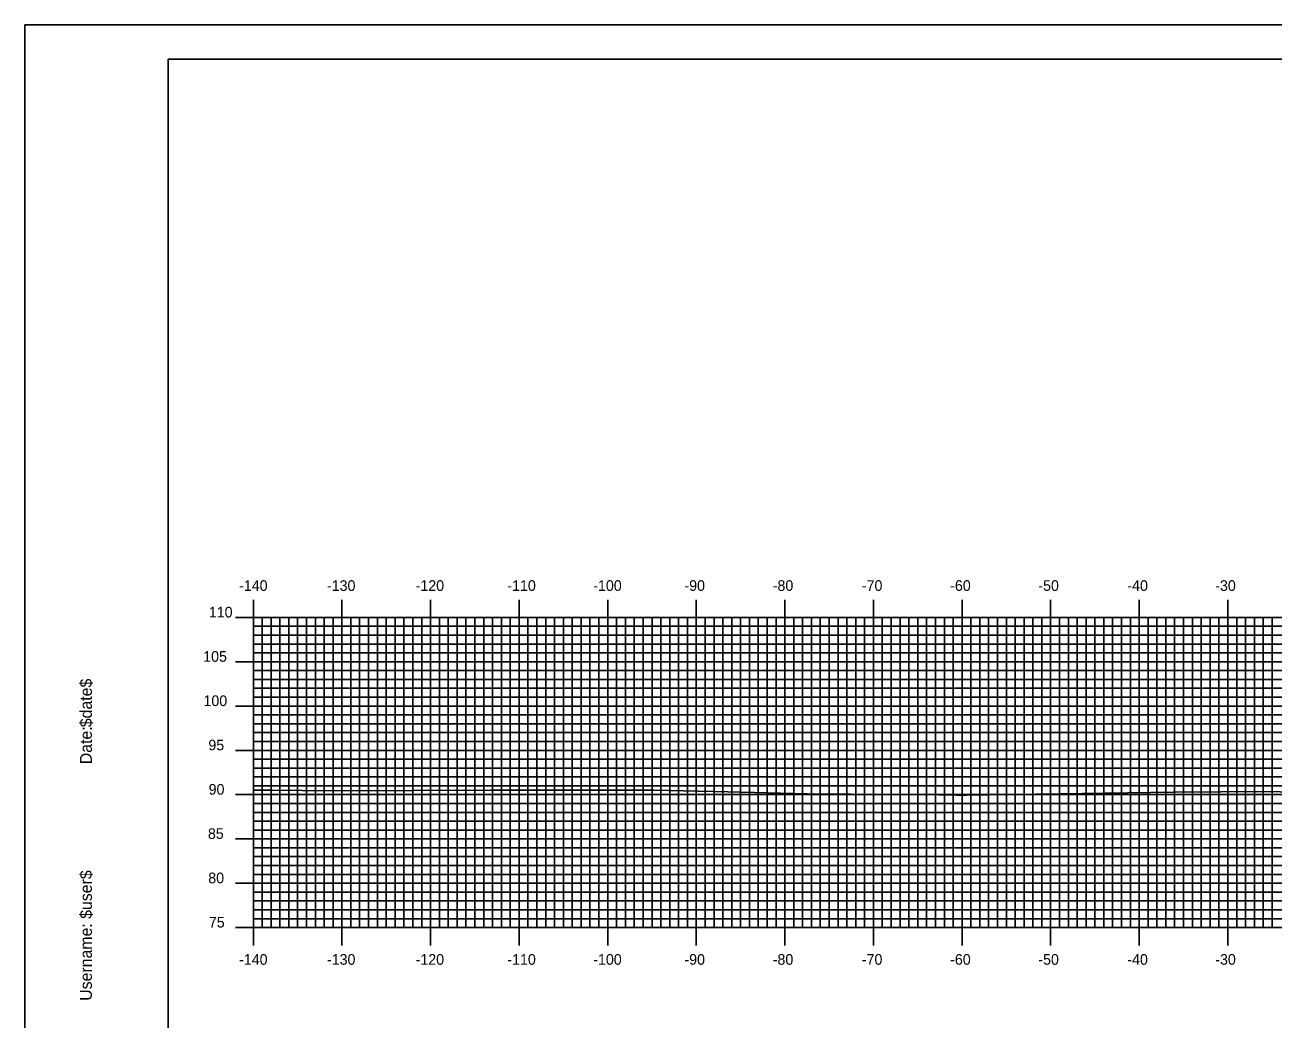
# Model space of a CAD drawing. Extents: x 854510 to 854853, y 364366 to 364586.
# Drawn here: x 854510 to 854650.8, y 364473.5 to 364585.7 of the extents above; entities that cross this region are included whole.
import ezdxf

# ---------------------------------------------------------------- set-up
doc = ezdxf.new("R2010")
doc.units = 0
for name, color, linetype in [('BORDER', 7, 'Continuous'), ('H_V ANNOTATION', 7, 'Continuous'), ('MAJOR', 7, 'Continuous'), ('MINOR', 7, 'Continuous'), ('PLOT BOUNDARY', 7, 'Continuous'), ('S_Roadway_Centerline', 7, 'Continuous')]:
    doc.layers.add(name, color=color, linetype=linetype)

msp = doc.modelspace()

# ---------------------------------------------------------------- linework, layer by layer
at = {"layer": 'BORDER'}
msp.add_lwpolyline([(854526.14, 364371.79), (854846.14, 364371.79), (854846.14, 364581.79), (854526.14, 364581.79)], close=True, dxfattribs=at)
at = {"layer": 'MAJOR'}
for p, q in [((854535.74, 364520.79), (854535.74, 364518.79)), ((854545.74, 364520.79), (854545.74, 364518.79)), ((854555.74, 364520.79), (854555.74, 364518.79)), ((854565.74, 364520.79), (854565.74, 364518.79)), ((854575.74, 364520.79), (854575.74, 364518.79)), ((854585.74, 364520.79), (854585.74, 364518.79)), ((854595.74, 364520.79), (854595.74, 364518.79)), ((854605.74, 364520.79), (854605.74, 364518.79)), ((854615.74, 364520.79), (854615.74, 364518.79)), ((854625.74, 364520.79), (854625.74, 364518.79)), ((854635.74, 364520.79), (854635.74, 364518.79)), ((854645.74, 364520.79), (854645.74, 364518.79)), ((854533.74, 364518.79), (854535.74, 364518.79)), ((854535.74, 364518.79), (854815.74, 364518.79)), ((854535.74, 364483.79), (854535.74, 364518.79)), ((854535.74, 364483.79), (854535.74, 364518.79)), ((854535.74, 364518.79), (854815.74, 364518.79)), ((854545.74, 364483.79), (854545.74, 364518.79)), ((854555.74, 364483.79), (854555.74, 364518.79)), ((854565.74, 364483.79), (854565.74, 364518.79)), ((854575.74, 364483.79), (854575.74, 364518.79)), ((854585.74, 364483.79), (854585.74, 364518.79)), ((854595.74, 364483.79), (854595.74, 364518.79)), ((854605.74, 364483.79), (854605.74, 364518.79)), ((854615.74, 364483.79), (854615.74, 364518.79)), ((854625.74, 364483.79), (854625.74, 364518.79)), ((854635.74, 364483.79), (854635.74, 364518.79)), ((854645.74, 364483.79), (854645.74, 364518.79)), ((854533.74, 364513.79), (854535.74, 364513.79)), ((854535.74, 364513.79), (854815.74, 364513.79)), ((854533.74, 364508.79), (854535.74, 364508.79)), ((854535.74, 364508.79), (854815.74, 364508.79)), ((854533.74, 364503.79), (854535.74, 364503.79)), ((854535.74, 364503.79), (854815.74, 364503.79)), ((854533.74, 364498.79), (854535.74, 364498.79)), ((854535.74, 364498.79), (854815.74, 364498.79)), ((854533.74, 364493.79), (854535.74, 364493.79)), ((854535.74, 364493.79), (854815.74, 364493.79)), ((854533.74, 364488.79), (854535.74, 364488.79)), ((854535.74, 364488.79), (854815.74, 364488.79)), ((854533.74, 364483.79), (854535.74, 364483.79)), ((854535.74, 364483.79), (854815.74, 364483.79)), ((854535.74, 364483.79), (854815.74, 364483.79)), ((854535.74, 364481.78), (854535.74, 364483.79)), ((854545.74, 364481.78), (854545.74, 364483.79)), ((854555.74, 364481.78), (854555.74, 364483.79)), ((854565.74, 364481.78), (854565.74, 364483.79)), ((854575.74, 364481.78), (854575.74, 364483.79)), ((854585.74, 364481.78), (854585.74, 364483.79)), ((854595.74, 364481.78), (854595.74, 364483.79)), ((854605.74, 364481.78), (854605.74, 364483.79)), ((854615.74, 364481.78), (854615.74, 364483.79)), ((854625.74, 364481.78), (854625.74, 364483.79)), ((854635.74, 364481.78), (854635.74, 364483.79)), ((854645.74, 364481.78), (854645.74, 364483.79))]:
    msp.add_line(p, q, dxfattribs=at)
at = {"layer": 'MINOR'}
for p, q in [((854535.74, 364517.79), (854815.74, 364517.79)), ((854535.74, 364517.79), (854537.75, 364517.79)), ((854536.74, 364483.79), (854536.74, 364518.79)), ((854537.74, 364483.79), (854537.74, 364518.79)), ((854538.74, 364483.79), (854538.74, 364518.79)), ((854539.74, 364483.79), (854539.74, 364518.79)), ((854540.74, 364483.79), (854540.74, 364518.79)), ((854541.74, 364483.79), (854541.74, 364518.79)), ((854542.74, 364483.79), (854542.74, 364518.79)), ((854543.74, 364483.79), (854543.74, 364518.79)), ((854544.74, 364483.79), (854544.74, 364518.79)), ((854546.74, 364483.79), (854546.74, 364518.79)), ((854547.74, 364483.79), (854547.74, 364518.79)), ((854548.74, 364483.79), (854548.74, 364518.79)), ((854549.74, 364483.79), (854549.74, 364518.79)), ((854550.74, 364483.79), (854550.74, 364518.79)), ((854551.74, 364483.79), (854551.74, 364518.79)), ((854552.74, 364483.79), (854552.74, 364518.79)), ((854553.74, 364483.79), (854553.74, 364518.79)), ((854554.74, 364483.79), (854554.74, 364518.79)), ((854556.74, 364483.79), (854556.74, 364518.79)), ((854557.74, 364483.79), (854557.74, 364518.79)), ((854558.74, 364483.79), (854558.74, 364518.79)), ((854559.74, 364483.79), (854559.74, 364518.79)), ((854560.74, 364483.79), (854560.74, 364518.79)), ((854561.74, 364483.79), (854561.74, 364518.79)), ((854562.74, 364483.79), (854562.74, 364518.79)), ((854563.74, 364483.79), (854563.74, 364518.79)), ((854564.74, 364483.79), (854564.74, 364518.79)), ((854566.74, 364483.79), (854566.74, 364518.79)), ((854567.74, 364483.79), (854567.74, 364518.79)), ((854568.74, 364483.79), (854568.74, 364518.79)), ((854569.74, 364483.79), (854569.74, 364518.79)), ((854570.74, 364483.79), (854570.74, 364518.79)), ((854571.74, 364483.79), (854571.74, 364518.79)), ((854572.74, 364483.79), (854572.74, 364518.79)), ((854573.74, 364483.79), (854573.74, 364518.79)), ((854574.74, 364483.79), (854574.74, 364518.79)), ((854576.74, 364483.79), (854576.74, 364518.79)), ((854577.74, 364483.79), (854577.74, 364518.79)), ((854578.74, 364483.79), (854578.74, 364518.79)), ((854579.74, 364483.79), (854579.74, 364518.79)), ((854580.74, 364483.79), (854580.74, 364518.79)), ((854581.74, 364483.79), (854581.74, 364518.79)), ((854582.74, 364483.79), (854582.74, 364518.79)), ((854583.74, 364483.79), (854583.74, 364518.79)), ((854584.74, 364483.79), (854584.74, 364518.79)), ((854586.74, 364483.79), (854586.74, 364518.79)), ((854587.74, 364483.79), (854587.74, 364518.79)), ((854588.74, 364483.79), (854588.74, 364518.79)), ((854589.74, 364483.79), (854589.74, 364518.79)), ((854590.74, 364483.79), (854590.74, 364518.79)), ((854591.74, 364483.79), (854591.74, 364518.79)), ((854592.74, 364483.79), (854592.74, 364518.79)), ((854593.74, 364483.79), (854593.74, 364518.79)), ((854594.74, 364483.79), (854594.74, 364518.79)), ((854596.74, 364483.79), (854596.74, 364518.79)), ((854597.74, 364483.79), (854597.74, 364518.79)), ((854598.74, 364483.79), (854598.74, 364518.79)), ((854599.74, 364483.79), (854599.74, 364518.79)), ((854600.74, 364483.79), (854600.74, 364518.79)), ((854601.74, 364483.79), (854601.74, 364518.79)), ((854602.74, 364483.79), (854602.74, 364518.79)), ((854603.74, 364483.79), (854603.74, 364518.79)), ((854604.74, 364483.79), (854604.74, 364518.79)), ((854606.74, 364483.79), (854606.74, 364518.79)), ((854607.74, 364483.79), (854607.74, 364518.79)), ((854608.74, 364483.79), (854608.74, 364518.79)), ((854609.74, 364483.79), (854609.74, 364518.79)), ((854610.74, 364483.79), (854610.74, 364518.79)), ((854611.74, 364483.79), (854611.74, 364518.79)), ((854612.74, 364483.79), (854612.74, 364518.79)), ((854613.74, 364483.79), (854613.74, 364518.79)), ((854614.74, 364483.79), (854614.74, 364518.79)), ((854616.74, 364483.79), (854616.74, 364518.79)), ((854617.74, 364483.79), (854617.74, 364518.79)), ((854618.74, 364483.79), (854618.74, 364518.79)), ((854619.74, 364483.79), (854619.74, 364518.79)), ((854620.74, 364483.79), (854620.74, 364518.79)), ((854621.74, 364483.79), (854621.74, 364518.79)), ((854622.74, 364483.79), (854622.74, 364518.79)), ((854623.74, 364483.79), (854623.74, 364518.79)), ((854624.74, 364483.79), (854624.74, 364518.79)), ((854626.74, 364483.79), (854626.74, 364518.79)), ((854627.74, 364483.79), (854627.74, 364518.79)), ((854628.74, 364483.79), (854628.74, 364518.79)), ((854629.74, 364483.79), (854629.74, 364518.79)), ((854630.74, 364483.79), (854630.74, 364518.79)), ((854631.74, 364483.79), (854631.74, 364518.79)), ((854632.74, 364483.79), (854632.74, 364518.79)), ((854633.74, 364483.79), (854633.74, 364518.79)), ((854634.74, 364483.79), (854634.74, 364518.79)), ((854636.74, 364483.79), (854636.74, 364518.79)), ((854637.74, 364483.79), (854637.74, 364518.79)), ((854638.74, 364483.79), (854638.74, 364518.79)), ((854639.74, 364483.79), (854639.74, 364518.79)), ((854640.74, 364483.79), (854640.74, 364518.79)), ((854641.74, 364483.79), (854641.74, 364518.79)), ((854642.74, 364483.79), (854642.74, 364518.79)), ((854643.74, 364483.79), (854643.74, 364518.79)), ((854644.74, 364483.79), (854644.74, 364518.79)), ((854646.74, 364483.79), (854646.74, 364518.79)), ((854647.74, 364483.79), (854647.74, 364518.79)), ((854648.74, 364483.79), (854648.74, 364518.79)), ((854649.74, 364483.79), (854649.74, 364518.79)), ((854650.74, 364483.79), (854650.74, 364518.79)), ((854535.74, 364516.79), (854815.74, 364516.79)), ((854535.74, 364516.79), (854537.75, 364516.79)), ((854535.74, 364515.79), (854815.74, 364515.79)), ((854535.74, 364515.79), (854537.75, 364515.79)), ((854535.74, 364514.79), (854815.74, 364514.79)), ((854535.74, 364514.79), (854537.75, 364514.79)), ((854535.74, 364512.79), (854815.74, 364512.79)), ((854535.74, 364512.79), (854537.75, 364512.79)), ((854535.74, 364511.79), (854815.74, 364511.79)), ((854535.74, 364511.79), (854537.75, 364511.79)), ((854535.74, 364510.79), (854815.74, 364510.79)), ((854535.74, 364510.79), (854537.75, 364510.79)), ((854535.74, 364509.79), (854815.74, 364509.79)), ((854535.74, 364509.79), (854537.75, 364509.79)), ((854535.74, 364507.79), (854815.74, 364507.79)), ((854535.74, 364507.79), (854537.75, 364507.79)), ((854535.74, 364506.79), (854815.74, 364506.79)), ((854535.74, 364506.79), (854537.75, 364506.79)), ((854535.74, 364505.79), (854815.74, 364505.79)), ((854535.74, 364505.79), (854537.75, 364505.79)), ((854535.74, 364504.79), (854815.74, 364504.79)), ((854535.74, 364504.79), (854537.75, 364504.79)), ((854535.74, 364502.79), (854815.74, 364502.79)), ((854535.74, 364502.79), (854537.75, 364502.79)), ((854535.74, 364501.79), (854815.74, 364501.79)), ((854535.74, 364501.79), (854537.75, 364501.79)), ((854535.74, 364500.79), (854815.74, 364500.79)), ((854535.74, 364500.79), (854537.75, 364500.79)), ((854535.74, 364499.79), (854815.74, 364499.79)), ((854535.74, 364499.79), (854537.75, 364499.79)), ((854535.74, 364497.79), (854815.74, 364497.79)), ((854535.74, 364497.79), (854537.75, 364497.79)), ((854535.74, 364496.79), (854815.74, 364496.79)), ((854535.74, 364496.79), (854537.75, 364496.79)), ((854535.74, 364495.79), (854815.74, 364495.79)), ((854535.74, 364495.79), (854537.75, 364495.79)), ((854535.74, 364494.79), (854815.74, 364494.79)), ((854535.74, 364494.79), (854537.75, 364494.79)), ((854535.74, 364492.79), (854815.74, 364492.79)), ((854535.74, 364492.79), (854537.75, 364492.79)), ((854535.74, 364491.79), (854815.74, 364491.79)), ((854535.74, 364491.79), (854537.75, 364491.79)), ((854535.74, 364490.79), (854815.74, 364490.79)), ((854535.74, 364490.79), (854537.75, 364490.79)), ((854535.74, 364489.79), (854815.74, 364489.79)), ((854535.74, 364489.79), (854537.75, 364489.79)), ((854535.74, 364487.79), (854815.74, 364487.79)), ((854535.74, 364487.79), (854537.75, 364487.79)), ((854535.74, 364486.79), (854815.74, 364486.79)), ((854535.74, 364486.79), (854537.75, 364486.79)), ((854535.74, 364485.79), (854815.74, 364485.79)), ((854535.74, 364485.79), (854537.75, 364485.79)), ((854535.74, 364484.79), (854815.74, 364484.79)), ((854535.74, 364484.79), (854537.75, 364484.79))]:
    msp.add_line(p, q, dxfattribs=at)
at = {"layer": 'PLOT BOUNDARY'}
msp.add_lwpolyline([(854509.96, 364365.67), (854849.96, 364365.67), (854849.96, 364585.67), (854509.96, 364585.67)], close=True, dxfattribs=at)
at = {"layer": 'S_Roadway_Centerline'}
msp.add_lwpolyline([(854535.74, 364499.29), (854537.72, 364499.3), (854544.77, 364499.23), (854562.54, 364499.31), (854562.76, 364499.32), (854562.85, 364499.31), (854563.22, 364499.31), (854577.85, 364499.29), (854580.93, 364499.31), (854589.29, 364499.11), (854598.28, 364498.9), (854613.13, 364498.76), (854614.49, 364498.75), (854615.1, 364498.73), (854616.26, 364498.74), (854631.9, 364498.94), (854639.57, 364499.07), (854650.32, 364499.13), (854659.66, 364498.9)], dxfattribs=at)

# ---------------------------------------------------------------- texts
at = {"layer": 'BORDER'}
for s, p in [('$date$', (854517.51, 364506.4)), ('Date:', (854517.51, 364502.22)), ('$user$', (854517.51, 364484.77)), ('Username:', (854517.51, 364475.52))]:
    msp.add_text(s, height=1.339, rotation=90, dxfattribs=at).set_placement(p)
at = {"layer": 'H_V ANNOTATION'}
for s, p in [('-140', (854534.13, 364521.79)), ('-130', (854544.05, 364521.79)), ('-120', (854554.06, 364521.79)), ('-110', (854564.41, 364521.79)), ('-100', (854574.11, 364521.79)), ('-90', (854584.4, 364521.79)), ('-80', (854594.37, 364521.79)), ('-70', (854604.43, 364521.79)), ('-60', (854614.4, 364521.79)), ('-50', (854624.35, 364521.79)), ('-40', (854634.4, 364521.79)), ('-30', (854644.32, 364521.79)), ('110', (854530.71, 364518.79)), ('105', (854530.08, 364513.79)), ('100', (854530.11, 364508.79)), ('95', (854530.66, 364503.79)), ('90', (854530.69, 364498.79)), ('85', (854530.61, 364493.79)), ('80', (854530.65, 364488.79)), ('75', (854530.72, 364483.79)), ('-140', (854534.13, 364479.59)), ('-130', (854544.05, 364479.59)), ('-120', (854554.06, 364479.59)), ('-110', (854564.41, 364479.59)), ('-100', (854574.11, 364479.59)), ('-90', (854584.4, 364479.59)), ('-80', (854594.37, 364479.59)), ('-70', (854604.43, 364479.59)), ('-60', (854614.4, 364479.59)), ('-50', (854624.35, 364479.59)), ('-40', (854634.4, 364479.59)), ('-30', (854644.32, 364479.59))]:
    msp.add_text(s, height=1.2, dxfattribs=at).set_placement(p)
at = {"layer": 'MAJOR'}
msp.add_text('-', height=0.012, dxfattribs=at).set_placement((854535.73, 364483.79))

doc.saveas('drawing.dxf')
